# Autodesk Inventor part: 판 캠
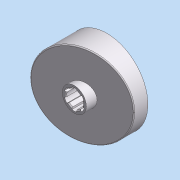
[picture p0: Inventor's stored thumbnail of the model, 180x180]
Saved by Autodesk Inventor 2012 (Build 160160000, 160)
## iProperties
Company: 한국ATC센터
Created: 2014-07
Part Number: 판 캠
Document SubType Name: 모델링
Designer: KYOUNG IL JANG
Material: 기본값
Mass: 86.8262 g
Surface Area: 331.302 cm^2
Volume: 86.8262 cm^3
Density: 1 g/cm^3
변환 표준: STEP AP214IS
파일 이름: C:\Users\SeoGD\Desktop\?쒗뿕\??stp
전처리기: Build: 253, Release: 2010 SP1 - Date: Wed 07/29/2009
전송 단위: 밀리미터
불확실성: 0.01
Author: KYOUNG IL JANG
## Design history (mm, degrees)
node "작업 평면4"
sketch "스케치1"
  geometry: C1 r 44.5 at (0, 0); 1 further point
  constraints: 1 centre point, 1 coincident
  dimensions: "d25" = 89 diameter of C1
extrude "돌출1" new body sketch "스케치1" distance "d1" = 40; taper "d2" = 0 deg
sketch "스케치2"
  geometry: L1 (-44.5, 15)-(44.5, 38.847); L2 (-44.5, 0)-(-44.5, 40) reference; L3 (-44.5, 40)-(44.5, 40) reference; L4 (44.5, 0)-(44.5, 40) reference; 1 further point
  constraints: 2 end point, 2 point on line
  dimensions: "d26" = 15 distance of L2.start L1.start; "d27" = 75 deg angle of L1 L2
extrude "돌출2" cut sketch "스케치2" stored distance "d5" = 40; taper "d6" = 0 deg
node "작업 평면1"
sketch "스케치3"
  geometry: C1 r 13 at (0, 0); 1 further point
  constraints: 1 centre point, 1 coincident
  dimensions: "d9" = 26 diameter of C1
extrude "돌출3" join sketch "스케치3" distance "d10" = 38; taper "d11" = 0 deg
hole "구멍1" diameter "d14" = 18; stored, may be unused: countersink angle "d18" = 90 deg, drill point angle "d20" = 118 deg; dims "d12" = 10, "d13" = 10, "d15" = 6, "d16" = 4, "d17" = 2, "d19" = 8
feature "쉘2" dims "d29" = 5
sketch "스케치6"
  geometry: C1 r 17.5 at (0, 0); C2 r 14 at (0, 0) reference; 1 further point
  constraints: 1 centre point, 1 coincident
  dimensions: "d28" = 35 diameter of C1
extrude "돌출4" join sketch "스케치6" stored distance "d30" = 38; taper "d31" = 0 deg
fillet "모깎기1" dims "d32" = 3
chamfer "모따기1" distance "d21" = 1; stored, may be unused: second distance "d22" = 2, angle "d23" = 45 deg
sketch "스케치7"
  geometry: L1 (-12.374, 12.374)-(-27.931, 27.931); A1 r 39.5 centre (0, 0) between (-27.931, 27.931) and (0, 39.5) reference; 2 further points
  constraints: 2 end point, 2 point on circle, 1 point on line, 1 vertical alignment, 2 other
  dimensions: "d33" = 45 deg dimension on point (0, 0) L1.start A1.end
feature "리브1" sketch "스케치7" dims "d34" = 5, "d35" = 1, "d36" = 0
fillet "모깎기2" dims "d37" = 3
sketch "스케치8"
  geometry: L1 (2.5, 10.712)-(2.5, 8.646); L2 (-2.5, 10.712)-(-2.5, 8.646); A1 r 11 centre (0, 0) between (2.5, 10.712) and (-2.5, 10.712); A2 r 9 centre (0, 0) between (2.5, 8.646) and (-2.5, 8.646) reference; 1 further point
  constraints: 4 end point, 4 point on circle, 2 parallel, 1 centre point, 1 coincident, 1 vertical
  dimensions: "d41" = 22 diameter of A1; "d42" = 5 distance between parallel lines of L1 L2
extrude "돌출5" cut sketch "스케치8" stored distance "d43" = 38; taper "d44" = 0 deg
fillet "모깎기3" dims "d48" = 1
node "솔리드1"
node "솔리드 본체"
node "곡면 본체"
pattern_circular "원형 패턴1" dims angle "d39" = 360 deg
pattern_circular "원형 패턴2" dims angle "d46" = 360 deg
node "솔리드2"
